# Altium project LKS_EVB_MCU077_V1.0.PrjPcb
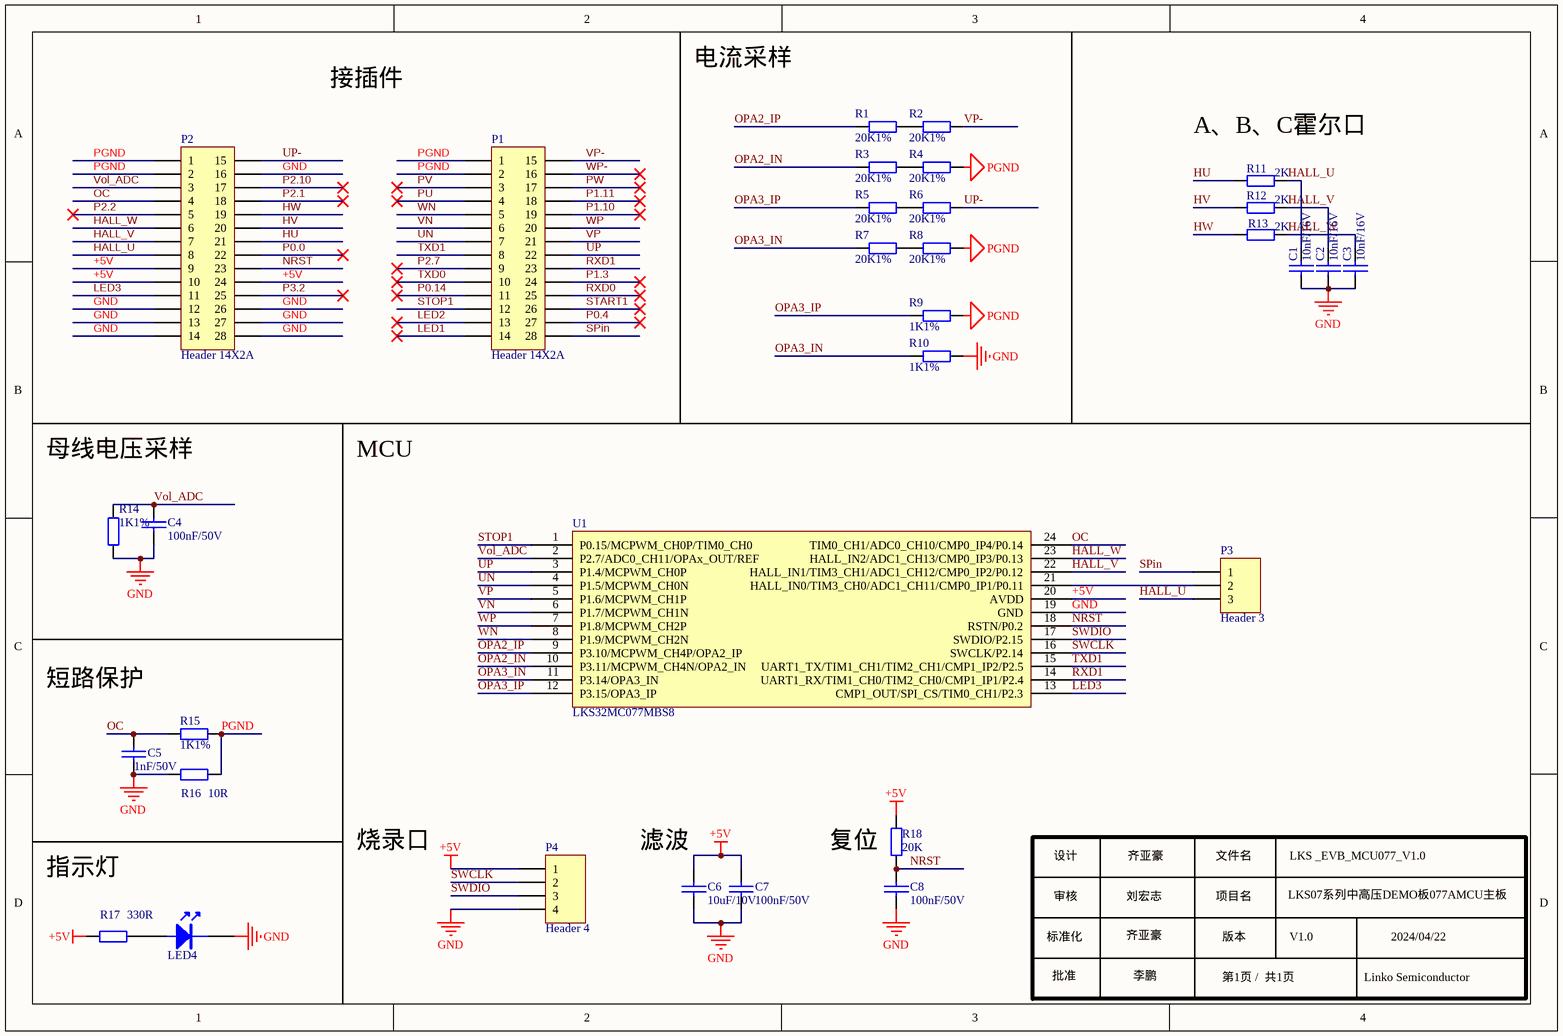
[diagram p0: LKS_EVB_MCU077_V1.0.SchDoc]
1 sheet, 32 parts. Net scope: global (net labels, ports and power ports of the same name join across sheets).
Board file: LKS_EVB_MCU077_V1.0.PcbDoc

## Sheet LKS_EVB_MCU077_V1.0.SchDoc
size A4; SheetNumber: 1; SheetTotal: 1

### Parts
C1  10nF/16V  [0603C]
C2  10nF/16V  [0603C]
C3  10nF/16V  [0603C]
C4  100nF/50V  [0603C]
C5  1nF/50V  [0603C]
C6  10uF/10V  [0603C]
C7  100nF/50V  [0603C]
C8  100nF/50V  [0603C]
LED4  LED  [LED 0603R]  (value not drawn)
P1  Header 14X2A  [HDR 2X14 底层]
P2  Header 14X2A  [HDR 2X14 底层]
P3  Header 3  [HDR 1X3]
P4  Header 4  [HDR 1X4]
R1  20K1%  [0603R]
R2  20K1%  [0603R]
R3  20K1%  [0603R]
R4  20K1%  [0603R]
R5  20K1%  [0603R]
R6  20K1%  [0603R]
R7  20K1%  [0603R]
R8  20K1%  [0603R]
R9  1K1%  [0603R]
R10  1K1%  [0603R]
R11  2K  [0603R]
R12  2K  [0603R]
R13  2K  [0603R]
R14  1K1%  [0603R]
R15  1K1%  [0603R]
R16  10R  [0603R]
R17  330R  [0603R]
R18  20K  [0603R]
U1  LKS32MC077MBS8  [SSOP24]

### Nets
+5V: C6.2 C7.2 P2.9 P2.10 P2.24 P4.1 R17.1 R18.2 U1.20(AVDD)
GND: C1.2 C2.2 C3.2 C4.1 C5.1 C6.1 C7.1 C8.2 LED4.2(K) P2.12 P2.13 P2.14 P2.16 P2.26 P2.27 P2.28 P4.4 R10.1 R14.1 R16.2 U1.19(GND)
PGND: P1.1 P1.2 P2.1 P2.2 R4.1 R8.1 R9.1 R15.2 R16.1
HALL_U: C1.1 P2.8 P3.3 R11.2
HALL_V: C2.1 P2.7 R12.2 U1.22(HALL_IN1/TIM3_CH1/ADC1_CH12/CMP0_IP2/P0.12)
HALL_W: C3.1 P2.6 R13.2 U1.23(HALL_IN2/ADC1_CH13/CMP0_IP3/P0.13)
HU: P2.21 R11.1
HV: P2.20 R12.1
HW: P2.19 R13.1
LED1: P1.14
LED2: P1.13
LED3: P2.11 U1.13(CMP1_OUT/SPI_CS/TIM0_CH1/P2.3)
NRST: C8.1 P2.23 R18.1 U1.18(RSTN/P0.2)
OC: C5.2 P2.4 R15.1 U1.24(TIM0_CH1/ADC0_CH10/CMP0_IP4/P0.14)
OPA2_IN: R3.2 U1.10(P3.11/MCPWM_CH4N/OPA2_IN)
OPA2_IP: R1.2 U1.9(P3.10/MCPWM_CH4P/OPA2_IP)
OPA3_IN: R7.2 R10.2 U1.11(P3.14/OPA3_IN)
OPA3_IP: R5.2 R9.2 U1.12(P3.15/OPA3_IP)
P0.0: P2.22
P0.4: P1.27
P0.14: P1.11
P1.3: P1.24
P1.10: P1.19
P1.11: P1.18
P2.1: P2.18
P2.2: P2.5
P2.7: P1.9
P2.10: P2.17
P3.2: P2.25
PU: P1.4
PV: P1.3
PW: P1.17
RXD0: P1.25
RXD1: P1.23 U1.14(UART1_RX/TIM1_CH0/TIM2_CH0/CMP1_IP1/P2.4)
SPin: P1.28 P3.1
START1: P1.26
STOP1: P1.12 U1.1(P0.15/MCPWM_CH0P/TIM0_CH0)
SWCLK: P4.2 U1.16(SWCLK/P2.14)
SWDIO: P4.3 U1.17(SWDIO/P2.15)
TXD0: P1.10
TXD1: P1.8 U1.15(UART1_TX/TIM1_CH1/TIM2_CH1/CMP1_IP2/P2.5)
UN: P1.7 U1.4(P1.5/MCPWM_CH0N)
UP: P1.22 U1.3(P1.4/MCPWM_CH0P)
UP-: P2.15 R6.1
VN: P1.6 U1.6(P1.7/MCPWM_CH1N)
Vol_ADC: C4.2 P2.3 R14.2 U1.2(P2.7/ADC0_CH11/OPAx_OUT/REF)
VP: P1.21 U1.5(P1.6/MCPWM_CH1P)
VP-: P1.15 R2.1
WN: P1.5 U1.8(P1.9/MCPWM_CH2N)
WP: P1.20 U1.7(P1.8/MCPWM_CH2P)
WP-: P1.16
NetLED4_1: LED4.1(A) R17.2
NetP3_2: P3.2 U1.21(HALL_IN0/TIM3_CH0/ADC1_CH11/CMP0_IP1/P0.11)
NetR1_1: R1.1 R2.2
NetR3_1: R3.1 R4.2
NetR5_1: R5.1 R6.2
NetR7_1: R7.1 R8.2

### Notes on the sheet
- 接插件
- 电流采样
- (near R11) A、B、C霍尔口
- 母线电压采样
- MCU
- 短路保护
- 烧录口
- (near C6) 滤波
- 复位
- 指示灯
- 设计
- 审核
- 刘宏志
- 齐亚豪
- 文件名
- 项目名
- LKS07系列中高压DEMO板077AMCU主板
- LKS _EVB_MCU077_V1.0
- 标准化
- 批准
- 李鹏
- 版本
- 第1页 /  共1页
- V1.0
- Linko Semiconductor
- 2024/04/22

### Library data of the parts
C1-C3 = CAP: Capacitor
C4-C8 = C: Capacitor
LED4 = LED: LED_Light
P1 P2 = Header 14X2A: Header, 14-Pin, Dual row
P3 = Header 3: Header, 3-Pin
P4 = Header 4: Header, 4-Pin
R1-R16 R18 = Res: Resistor; Value: K
R17 = Res: Resistor; Value: 330
U1 = LKS32MC077MBS8: 芯片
